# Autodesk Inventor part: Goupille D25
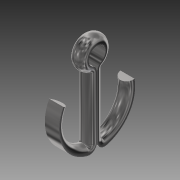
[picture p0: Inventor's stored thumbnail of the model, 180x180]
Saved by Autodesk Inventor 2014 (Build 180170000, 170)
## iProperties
Created: 2015-09
Part Number: Goupille D25
Material: Générique
Document SubType Name: Modeling
Designer: OL
Density: 1 g/cm^3
Appearance: Par défaut
Author: OL
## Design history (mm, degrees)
sketch "Esquisse1"
  geometry: L1 (-0.1, -27.11)-(-0.1, -2.213); L2 (0.1, -27.11)-(0.1, -2.213); A1 r 3.5 centre (0, 3.5) between (1.669, 0.424) and (-1.669, 0.424); A2 r 3 centre (3.1, -2.213) between (1.669, 0.424) and (0.1, -2.213); A3 r 3 centre (-3.1, -2.213) between (-0.1, -2.213) and (-1.669, 0.424); A4 r 15.5 centre (0, -15) between (-13.714, -7.777) and (-3.844, -30.016); A5 r 15.5 centre (0, -15) between (3.844, -30.016) and (15.263, -12.302); A6 r 3 centre (-3.1, -27.11) between (-3.844, -30.016) and (-0.1, -27.11); A7 r 3 centre (3.1, -27.11) between (0.1, -27.11) and (3.844, -30.016); 5 further points
  constraints: 19 point on circle, 8 tangent, 7 centre point, 4 end point, 4 point on line, 2 equal radius, 1 parallel, 1 vertical
  dimensions: "d2" = 7 diameter of A1; "d3" = 15 distance of A4.centre point (0, 0); "d4" = 0.2 distance between parallel lines of L2 L1; "d5" = 0.1 distance from line of point (0, 0) L1; "d6" = 3 radius of A2; "d7" = 0 horizontal distance of point (0, 0) A1.centre; "d8" = 3 radius of A6; "d12" = 15.5 radius of A4; "d13" = 15.5 radius of A5
sketch "Esquisse3"
  geometry: L1 (0, 7)-(0, 0.424) reference; L2 (-2.9, 7)-(2.9, 7); A1 r 2.9 centre (0, 7) between (2.9, 7) and (-2.9, 7); 2 further points
  constraints: 2 end point, 2 point on circle, 1 centre point, 1 coincident, 1 perpendicular
  dimensions: "d10" = 2.9 radius of A1
feature "Balayage2" sketch "Esquisse1", "Esquisse3" dims "d17" = 0
node "Solide2"
